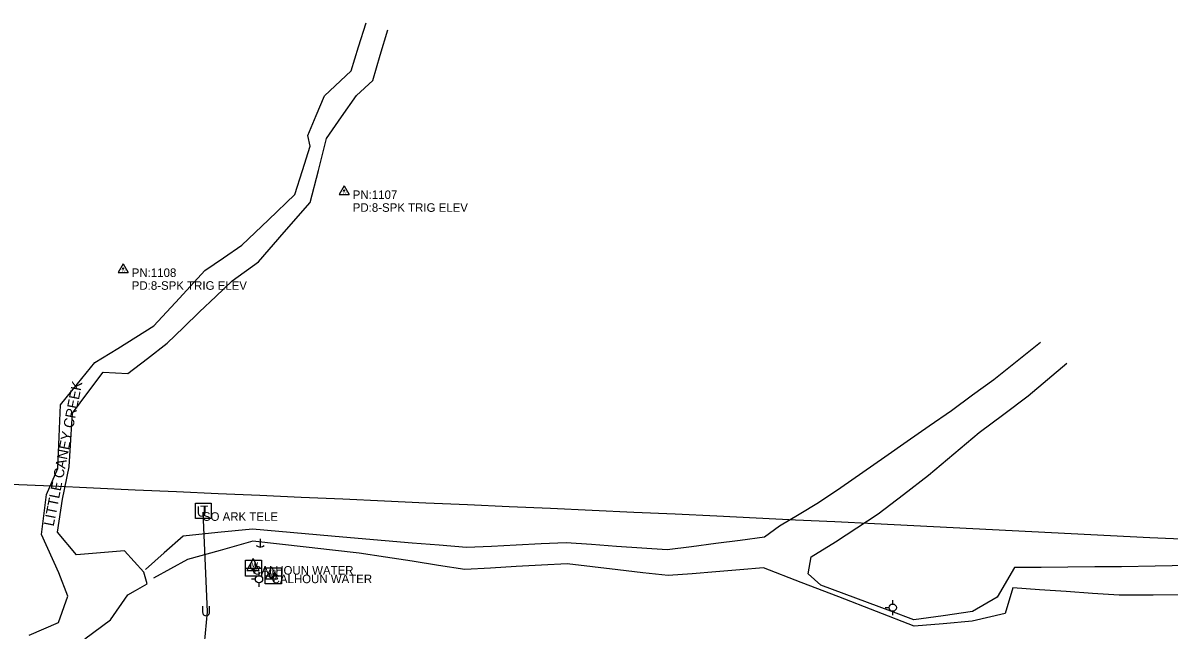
# Model space of a CAD drawing. Extents: x 1138803 to 1169983, y 1655906 to 1658226.
# Drawn here: x 1149238 to 1149908, y 1657498 to 1657853 of the extents above; entities that cross this region are included whole.
import ezdxf

# ---------------------------------------------------------------- set-up
doc = ezdxf.new("R2010")
doc.units = 0
for name, color, linetype in [('Default', 7, 'Continuous'), ('R_Annotation', 7, 'Continuous'), ('S_DITCHLINE', 7, 'Continuous'), ('S_SECONDARY_CTL', 7, 'Continuous'), ('S_SECONDARY_CTL_ANNOT', 7, 'Continuous'), ('S_STREAM', 7, 'Continuous'), ('S_TELEPHONE_UTILITIES', 7, 'Continuous'), ('S_TREE', 7, 'Continuous'), ('S_UNDERGROUND_CABLE', 7, 'Continuous'), ('S_UNDERGROUND_CABLE_ANNOT', 7, 'Continuous'), ('S_UTILITY_POLE', 7, 'Continuous'), ('S_UTILITY_POLE_ANNOT', 7, 'Continuous'), ('S_WATER_UTILITIES', 7, 'Continuous')]:
    doc.layers.add(name, color=color, linetype=linetype)

msp = doc.modelspace()

# ---------------------------------------------------------------- linework, layer by layer
at = {"layer": 'S_DITCHLINE'}
for points in [[(1149832.39, 1657665.83), (1149818.75, 1657654.91), (1149805.12, 1657643.99), (1149792.79, 1657634.97), (1149780.47, 1657625.94), (1149767.5, 1657616.91), (1149754.54, 1657607.88), (1149741.58, 1657598.85), (1149728.62, 1657589.81), (1149715.75, 1657580.99), (1149702.88, 1657572.17), (1149691.41, 1657565.39), (1149679.94, 1657558.61), (1149671.26, 1657552.02), (1149657.02, 1657550.17), (1149642.79, 1657548.31), (1149628.56, 1657546.46), (1149614.32, 1657544.6), (1149599.59, 1657545.66), (1149584.86, 1657546.72), (1149570.13, 1657547.78), (1149555.4, 1657548.84), (1149540.84, 1657548.12), (1149526.28, 1657547.41), (1149511.71, 1657546.69), (1149497.15, 1657545.97), (1149481.31, 1657547.32), (1149465.48, 1657548.67), (1149449.65, 1657550.01), (1149433.81, 1657551.36), (1149418.39, 1657552.71), (1149402.97, 1657554.07), (1149387.55, 1657555.42), (1149372.13, 1657556.78), (1149351.87, 1657554.73), (1149331.61, 1657552.69), (1149320.62, 1657542.99), (1149309.64, 1657533.28)], [(1149919.29, 1657535.62), (1149899.49, 1657535.21), (1149879.7, 1657534.8), (1149864.1, 1657534.68), (1149848.5, 1657534.55), (1149832.91, 1657534.43), (1149817.31, 1657534.31), (1149807.22, 1657517.05), (1149792.82, 1657508.59), (1149775.69, 1657506.2), (1149758.56, 1657503.81), (1149744.95, 1657508.87), (1149731.34, 1657513.93), (1149717.73, 1657519), (1149704.12, 1657524.06), (1149696.75, 1657530.64), (1149698.47, 1657540.59), (1149712.71, 1657549.43), (1149725.17, 1657557.62), (1149737.62, 1657565.81), (1149752.37, 1657577.05), (1149767.12, 1657588.29), (1149781.91, 1657600.79), (1149796.71, 1657613.3), (1149811.02, 1657624.02), (1149825.32, 1657634.74), (1149836.61, 1657644.24), (1149847.89, 1657653.73)], [(1149918.12, 1657518.35), (1149898.26, 1657518.23), (1149878.4, 1657518.11), (1149862.88, 1657519.21), (1149847.37, 1657520.31), (1149831.85, 1657521.4), (1149816.33, 1657522.5), (1149811.8, 1657507.47), (1149792.5, 1657502.92), (1149775.59, 1657501.51), (1149758.68, 1657500.11), (1149736.67, 1657508.63), (1149714.66, 1657517.16), (1149692.65, 1657525.68), (1149670.65, 1657534.21), (1149656.74, 1657533.06), (1149642.83, 1657531.9), (1149628.92, 1657530.75), (1149615.01, 1657529.6), (1149600.27, 1657531.32), (1149585.53, 1657533.05), (1149570.78, 1657534.77), (1149556.04, 1657536.49), (1149541.08, 1657535.68), (1149526.12, 1657534.86), (1149511.16, 1657534.04), (1149496.2, 1657533.23), (1149480.78, 1657535.62), (1149465.36, 1657538.02), (1149449.94, 1657540.41), (1149434.52, 1657542.81), (1149418.98, 1657544.53), (1149403.45, 1657546.25), (1149387.91, 1657547.98), (1149372.37, 1657549.7), (1149353.34, 1657544.37), (1149334.31, 1657539.04), (1149314.3, 1657528.07)]]:
    msp.add_lwpolyline(points, dxfattribs=at)
at = {"layer": 'S_SECONDARY_CTL'}
for p, q in [((1149425.75, 1657757.27), (1149422.74, 1657752.32)), ((1149425.75, 1657757.27), (1149428.7, 1657752.32)), ((1149422.74, 1657752.32), (1149428.7, 1657752.32)), ((1149296.67, 1657711.71), (1149293.66, 1657706.76)), ((1149296.67, 1657711.71), (1149299.61, 1657706.76)), ((1149293.66, 1657706.76), (1149299.61, 1657706.76))]:
    msp.add_line(p, q, dxfattribs=at)
for centre, radius in [((1149425.75, 1657754.66), 0.311), ((1149425.75, 1657754.66), 0.183), ((1149425.75, 1657754.66), 0.103), ((1149296.67, 1657709.1), 0.311), ((1149296.67, 1657709.1), 0.183), ((1149296.67, 1657709.1), 0.103)]:
    msp.add_circle(centre, radius, dxfattribs=at)
at = {"layer": 'S_STREAM'}
for points in [[(1149241.68, 1657494.79), (1149258.94, 1657502.25), (1149264.28, 1657517.68), (1149259.05, 1657531.2), (1149249.01, 1657553.71), (1149251.87, 1657577.05), (1149258.57, 1657592.2), (1149259.27, 1657610.78), (1149259.96, 1657629.36), (1149270.04, 1657641.73), (1149280.11, 1657654.1), (1149293.45, 1657662.28), (1149314.51, 1657675.46), (1149329.46, 1657691.69), (1149344.42, 1657707.93), (1149355.19, 1657715.33), (1149365.96, 1657722.74), (1149381.46, 1657737.51), (1149396.96, 1657752.28), (1149401.44, 1657766.39), (1149405.92, 1657780.5), (1149404.57, 1657786.79), (1149409.41, 1657798.35), (1149414.26, 1657809.9), (1149429.83, 1657824.54), (1149434.19, 1657838.53), (1149438.55, 1657852.52)], [(1149274.34, 1657492.65), (1149289.26, 1657503.87), (1149299.3, 1657518.38), (1149303.89, 1657520.86), (1149310.65, 1657524.73), (1149308.65, 1657531.67), (1149297.5, 1657544.19), (1149283.43, 1657542.94), (1149269.37, 1657541.7), (1149258.27, 1657554.92), (1149261.23, 1657574.3), (1149265.01, 1657593.2), (1149266.05, 1657608.89), (1149267.1, 1657624.57), (1149276, 1657636.55), (1149284.91, 1657648.53), (1149299.32, 1657647.73), (1149310.83, 1657656.56), (1149322.34, 1657665.39), (1149331.82, 1657674.51), (1149341.3, 1657683.64), (1149350.78, 1657692.76), (1149360.26, 1657701.88), (1149375.59, 1657712.9), (1149390.68, 1657730.23), (1149405.77, 1657747.56), (1149410.64, 1657766.31), (1149415.5, 1657785.07), (1149424.26, 1657797.62), (1149433.02, 1657810.18), (1149442.53, 1657818.82), (1149446.84, 1657833.69), (1149451.15, 1657848.56)]]:
    msp.add_lwpolyline(points, dxfattribs=at)
at = {"layer": 'S_TELEPHONE_UTILITIES'}
msp.add_lwpolyline([(1149338.98, 1657563.02), (1149338.98, 1657572.02), (1149347.98, 1657572.02), (1149347.98, 1657563.02)], close=True, dxfattribs=at)
at = {"layer": 'S_TREE'}
msp.add_lwpolyline([(1149919.36, 1657550.65), (1149896.37, 1657551.79), (1149873.37, 1657552.94), (1149850.38, 1657554.08), (1149827.39, 1657555.23), (1149804.39, 1657556.37), (1149781.4, 1657557.52), (1149758.41, 1657558.66), (1149735.41, 1657559.81), (1149712.42, 1657560.95), (1149689.43, 1657562.09), (1149666.43, 1657563.24), (1149643.44, 1657564.38), (1149619.16, 1657565.47), (1149594.89, 1657566.56), (1149570.61, 1657567.65), (1149546.34, 1657568.74), (1149522.06, 1657569.83), (1149497.79, 1657570.92), (1149473.51, 1657572.01), (1149449.23, 1657573.1), (1149424.96, 1657574.19), (1149400.68, 1657575.28), (1149376.41, 1657576.37), (1149352.13, 1657577.46), (1149327.85, 1657578.55), (1149303.58, 1657579.64), (1149279.3, 1657580.73), (1149255.03, 1657581.82), (1149230.75, 1657582.91)], dxfattribs=at)
at = {"layer": 'S_UNDERGROUND_CABLE'}
for p, q in [((1149343.22, 1657566.64), (1149345.79, 1657508.45)), ((1149372.48, 1657539.72), (1149368.96, 1657532.63)), ((1149372.48, 1657539.72), (1149375.97, 1657532.63)), ((1149368.96, 1657532.63), (1149375.97, 1657532.63)), ((1149371.28, 1657533.87), (1149371.28, 1657536.31)), ((1149371.9, 1657533.21), (1149371.28, 1657533.87)), ((1149373.1, 1657533.21), (1149371.9, 1657533.21)), ((1149373.65, 1657533.87), (1149373.1, 1657533.21)), ((1149373.65, 1657536.31), (1149373.65, 1657533.87)), ((1149383.36, 1657534.75), (1149379.83, 1657527.66)), ((1149382.16, 1657528.9), (1149382.16, 1657531.34)), ((1149383.36, 1657534.75), (1149386.85, 1657527.66)), ((1149384.52, 1657531.34), (1149384.52, 1657528.9)), ((1149379.83, 1657527.66), (1149386.85, 1657527.66)), ((1149382.78, 1657528.24), (1149382.16, 1657528.9)), ((1149383.98, 1657528.24), (1149382.78, 1657528.24)), ((1149384.52, 1657528.9), (1149383.98, 1657528.24)), ((1149345.79, 1657508.45), (1149343.42, 1657483.52))]:
    msp.add_line(p, q, dxfattribs=at)
at = {"layer": 'S_UTILITY_POLE'}
for p, q in [((1149376.68, 1657551.05), (1149376.68, 1657546.32)), ((1149375.99, 1657529.62), (1149375.99, 1657531.87)), ((1149373.89, 1657527.49), (1149371.57, 1657527.49)), ((1149376.06, 1657523.07), (1149376.06, 1657525.4)), ((1149744.06, 1657510.88), (1149741.73, 1657510.88)), ((1149746.15, 1657513.01), (1149746.15, 1657515.26)), ((1149746.23, 1657506.46), (1149746.23, 1657508.79))]:
    msp.add_line(p, q, dxfattribs=at)
for centre in [(1149375.99, 1657527.51), (1149746.15, 1657510.9)]:
    msp.add_circle(centre, 2.13, dxfattribs=at)
msp.add_arc((1149376.74, 1657549.75), 3.41, 226.39718, 313.60282, dxfattribs=at)
at = {"layer": 'S_WATER_UTILITIES'}
for p, q in [((1149368.04, 1657538.71), (1149377.45, 1657538.71)), ((1149368.04, 1657529.29), (1149368.04, 1657538.71)), ((1149377.45, 1657538.71), (1149377.45, 1657529.29)), ((1149368.04, 1657534.02), (1149377.45, 1657534.02)), ((1149379.67, 1657534.26), (1149389.09, 1657534.26)), ((1149379.67, 1657524.84), (1149379.67, 1657534.26)), ((1149389.09, 1657534.26), (1149389.09, 1657524.84)), ((1149377.45, 1657529.29), (1149368.04, 1657529.29)), ((1149379.67, 1657529.57), (1149389.09, 1657529.57)), ((1149389.09, 1657524.84), (1149379.67, 1657524.84))]:
    msp.add_line(p, q, dxfattribs=at)

# ---------------------------------------------------------------- texts
at = {"layer": 'Default'}
for p in [(1149339.59, 1657564.09), (1149342.16, 1657505.91)]:
    msp.add_text('U', height=6, rotation=360, dxfattribs=at).set_placement(p)
at = {"layer": 'R_Annotation'}
msp.add_text('LITTLE CANEY CREEK', height=6, rotation=78.69566, dxfattribs=at).set_placement((1149255.99, 1657558.15))
at = {"layer": 'S_SECONDARY_CTL'}
for p in [(1149424.55, 1657752.65), (1149295.46, 1657707.09)]:
    msp.add_text('TV', height=1.5, rotation=360, dxfattribs=at).set_placement(p)
at = {"layer": 'S_SECONDARY_CTL_ANNOT'}
for s, p in [('PN:1107', (1149430.75, 1657749.66)), ('PD:8-SPK TRIG ELEV', (1149430.75, 1657742.16)), ('PN:1108', (1149301.67, 1657704.1)), ('PD:8-SPK TRIG ELEV', (1149301.67, 1657696.6))]:
    msp.add_text(s, height=5, dxfattribs=at).set_placement(p)
at = {"layer": 'S_TELEPHONE_UTILITIES'}
msp.add_text('T', height=6, rotation=360, dxfattribs=at).set_placement((1149341.54, 1657564.52))
at = {"layer": 'S_UNDERGROUND_CABLE_ANNOT'}
msp.add_text('SO ARK TELE', height=5, dxfattribs=at).set_placement((1149343.22, 1657561.64))
at = {"layer": 'S_UTILITY_POLE_ANNOT'}
for p in [(1149372.48, 1657530.19), (1149383.36, 1657525.22)]:
    msp.add_text('CALHOUN WATER', height=5, dxfattribs=at).set_placement(p)
at = {"layer": 'S_WATER_UTILITIES'}
for s, p in [('W', (1149371.59, 1657534.55)), ('V', (1149371.82, 1657530.49)), ('W', (1149383.22, 1657530.1)), ('V', (1149383.46, 1657526.04))]:
    msp.add_text(s, height=3, rotation=360, dxfattribs=at).set_placement(p)

doc.saveas('drawing.dxf')
